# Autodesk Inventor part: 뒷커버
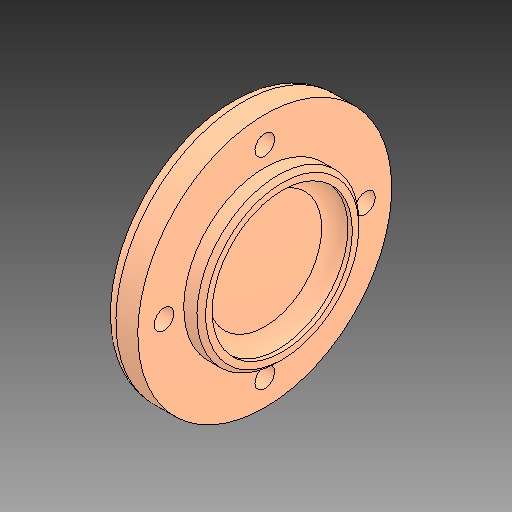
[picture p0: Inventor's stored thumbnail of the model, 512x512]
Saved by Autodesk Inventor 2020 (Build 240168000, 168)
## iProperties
Created: 2024-08
Part Number: 뒷커버
Material: 알루미늄 6061
Document SubType Name: Modeling
Designer: 1강의실14
Density: 2.7 g/cm^3
Appearance: 기본값
Author: jhkim
Sending System: Autodesk Inventor 2025
Preprocessor: ST-DEVELOPER v20
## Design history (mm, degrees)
feature "솔리드1"
node "솔리드2"
